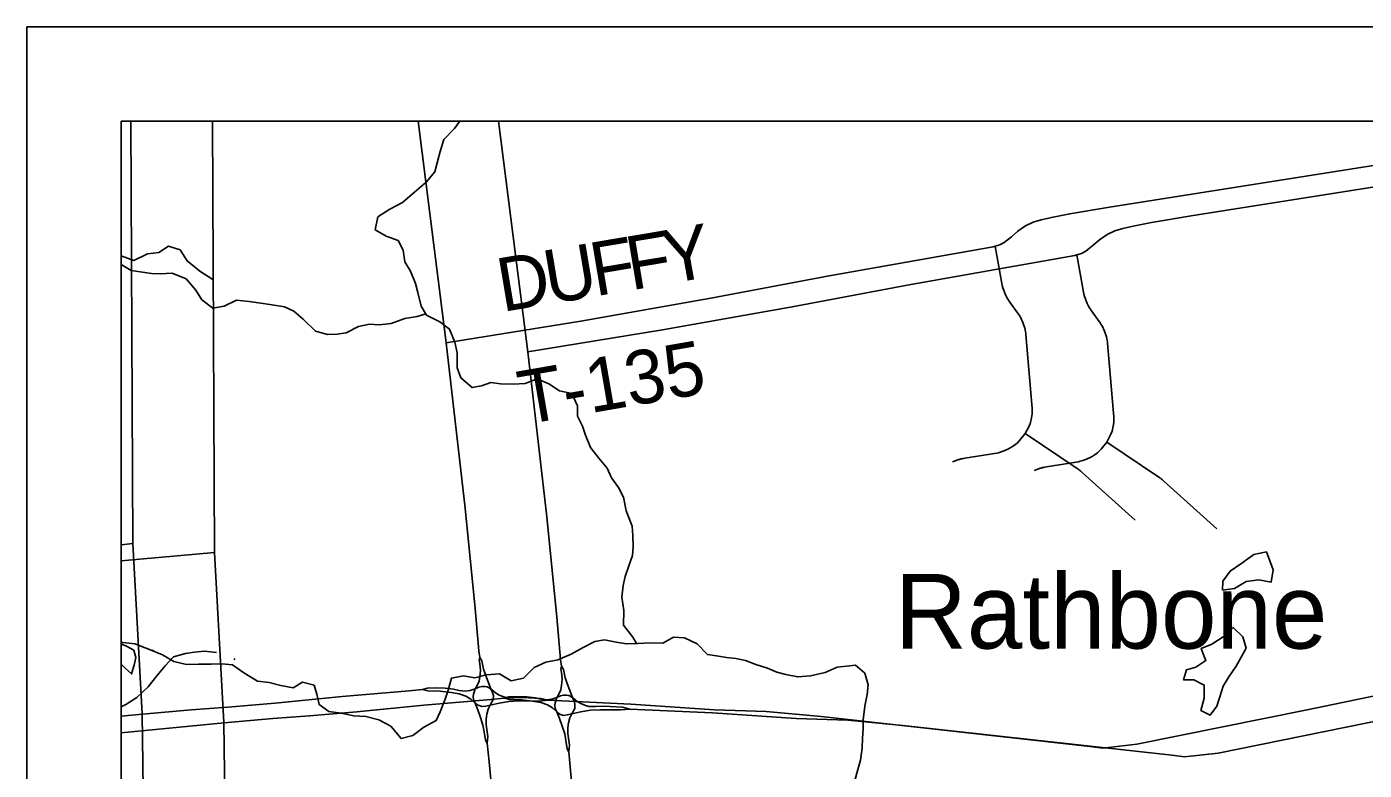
# Model space of a CAD drawing. Extents: x -38.2 to 41.9, y -4 to 24.9.
# Drawn here: x 2 to 3.416, y 20.213 to 21 of the extents above; entities that cross this region are included whole.
import ezdxf

# ---------------------------------------------------------------- set-up
doc = ezdxf.new("R2010")
doc.units = 0
for name, color, linetype in [('GM_X_County_Road', 7, 'Continuous'), ('GM_X_Interchange_Ramps', 7, 'Continuous'), ('GM_X_Minor_Lake', 7, 'Continuous'), ('GM_X_Minor_River', 7, 'Continuous'), ('GM_X_Minor_River_Text', 7, 'Continuous'), ('GM_X_State_Location', 7, 'Continuous'), ('GM_X_Township_Road', 7, 'Continuous'), ('GM_X_Township_Road_Text', 7, 'Continuous'), ('GM_X_Unincorporated_Text', 7, 'Continuous'), ('SH_Cut_Line', 7, 'Continuous'), ('SH_Data', 7, 'Continuous')]:
    doc.layers.add(name, color=color, linetype=linetype)

msp = doc.modelspace()

# ---------------------------------------------------------------- linework, layer by layer
at = {"layer": 'GM_X_County_Road'}
msp.add_line((2.1, 20.2698), (2.1225, 20.272), dxfattribs=at)
for points in [[(2.4799, 20.3319), (2.4788, 20.3391), (2.4748, 20.3839), (2.4641, 20.4903), (2.444, 20.6651), (2.4144, 20.9)], [(2.475, 20.2988), (2.4766, 20.3017), (2.4789, 20.307), (2.4802, 20.3143), (2.4805, 20.3187), (2.4798, 20.3255), (2.479, 20.3291), (2.4799, 20.3319)], [(2.4914, 20.299), (2.4869, 20.3108), (2.4837, 20.3198), (2.4818, 20.3286), (2.4799, 20.3319)], [(2.1225, 20.272), (2.1741, 20.2765), (2.2129, 20.2796), (2.263, 20.2837), (2.334, 20.2907), (2.4051, 20.2968), (2.4191, 20.2981)], [(2.4191, 20.2981), (2.4244, 20.2997), (2.4335, 20.3), (2.443, 20.2996), (2.452, 20.2984), (2.458, 20.297), (2.4641, 20.2965), (2.4694, 20.2972), (2.475, 20.2988)], [(2.4191, 20.2981), (2.4248, 20.2968), (2.4377, 20.2965), (2.4493, 20.2949), (2.4578, 20.2935), (2.4648, 20.2911), (2.4702, 20.2879), (2.4748, 20.2837)], [(2.4748, 20.2837), (2.4732, 20.2874), (2.4727, 20.2907), (2.473, 20.2932), (2.4736, 20.2953), (2.475, 20.2988)], [(2.475, 20.2988), (2.4786, 20.3005), (2.4819, 20.3013), (2.485, 20.3014), (2.4874, 20.3009), (2.4914, 20.299)], [(2.4907, 20.2817), (2.4938, 20.2874), (2.4941, 20.2917), (2.4931, 20.2949), (2.4914, 20.299)], [(2.4914, 20.299), (2.4962, 20.2946), (2.5001, 20.2923), (2.5052, 20.2905), (2.5088, 20.2895), (2.5161, 20.2892), (2.5244, 20.2896), (2.5312, 20.2894), (2.5442, 20.2887), (2.5521, 20.2867)], [(2.5521, 20.2867), (2.6398, 20.2826), (2.7282, 20.2767), (2.7828, 20.2748), (2.8413, 20.2694), (3.126, 20.2377), (3.1394, 20.236), (3.1753, 20.2401), (3.3558, 20.2767), (3.47, 20.3002), (3.5, 20.3062), (3.5061, 20.3069)], [(2.4748, 20.2837), (2.4779, 20.2814), (2.4818, 20.28), (2.486, 20.2804), (2.4907, 20.2817)], [(2.4876, 20.2415), (2.4859, 20.2446), (2.4844, 20.2533), (2.4831, 20.2604), (2.4806, 20.2685), (2.4775, 20.2765), (2.4748, 20.2837)], [(2.4876, 20.2415), (2.4882, 20.2483), (2.4863, 20.2609), (2.4864, 20.2668), (2.4872, 20.2722), (2.4885, 20.2773), (2.4907, 20.2817)], [(2.4907, 20.2817), (2.5003, 20.2838), (2.5106, 20.2855), (2.5209, 20.286), (2.5422, 20.2857), (2.5521, 20.2867)], [(2.7015, 19.4355), (2.6464, 19.9755), (2.6416, 20.0251), (2.6399, 20.0297), (2.6373, 20.0331), (2.6311, 20.0337), (2.5636, 20.0217), (2.531, 20.0146), (2.5216, 20.0146), (2.5162, 20.0164), (2.5108, 20.0203), (2.5077, 20.0277), (2.4972, 20.143), (2.4895, 20.2217), (2.4876, 20.2415)]]:
    msp.add_lwpolyline(points, dxfattribs=at)
at = {"layer": 'GM_X_Interchange_Ramps'}
for points in [[(2.1103, 20.9), (2.1, 20.9), (2.1, 20.4515), (2.1124, 20.4526)], [(2.1968, 20.9), (2.1, 20.9), (2.1, 20.4344), (2.1989, 20.4434)], [(2.1, 20.4515), (2.1, 14.1636), (2.1303, 14.1626), (2.1303, 14.1722), (2.1335, 15.4167), (2.1334, 15.4951), (2.1328, 15.831), (2.1521, 16.6664), (2.1489, 17.073), (2.1485, 17.1357), (2.1484, 17.1455), (2.1486, 17.1556), (2.1569, 17.5704), (2.1549, 17.5972), (2.1521, 17.6416), (2.1422, 17.7563), (2.1427, 17.838), (2.1429, 18.1709), (2.1421, 18.2952), (2.138, 18.8976), (2.1339, 19.396), (2.1223, 20.2725), (2.1124, 20.4526)], [(2.1, 20.4344), (2.1, 14.1575), (2.2168, 14.1534), (2.2168, 14.163), (2.22, 15.4075), (2.2199, 15.4859), (2.2193, 15.8218), (2.2386, 16.6572), (2.2354, 17.0638), (2.235, 17.1266), (2.2349, 17.1363), (2.2351, 17.1464), (2.2434, 17.5612), (2.2414, 17.5881), (2.2386, 17.6324), (2.2287, 17.7471), (2.2291, 17.8288), (2.2294, 18.1617), (2.2286, 18.286), (2.2245, 18.8884), (2.2204, 19.3868), (2.2088, 20.2633), (2.1989, 20.4434)]]:
    msp.add_lwpolyline(points, close=True, dxfattribs=at)
for points in [[(5.0183, 19.2401), (5.0869, 20.3321), (5.1243, 20.9), (2.1103, 20.9), (2.1124, 20.4526), (2.1223, 20.2725), (2.1339, 19.396)], [(5.1048, 19.2309), (5.1734, 20.3229), (5.2114, 20.9), (2.1968, 20.9), (2.1989, 20.4434), (2.2088, 20.2633), (2.2204, 19.3868)]]:
    msp.add_lwpolyline(points, dxfattribs=at)
at = {"layer": 'GM_X_Minor_Lake'}
for points in [[(3.2661, 20.4034), (3.2787, 20.4052), (3.2912, 20.4124), (3.3045, 20.4143), (3.3178, 20.4119), (3.3197, 20.4248), (3.3126, 20.4438)], [(3.3126, 20.4438), (3.2993, 20.4412), (3.2867, 20.4321), (3.2742, 20.4235), (3.2665, 20.4129), (3.2661, 20.4034)], [(3.2914, 20.3419), (3.2876, 20.354), (3.2774, 20.3639), (3.2668, 20.3541), (3.255, 20.3461), (3.2436, 20.3416), (3.2467, 20.3332)], [(3.2467, 20.3332), (3.2485, 20.3287), (3.2378, 20.3219), (3.2279, 20.3189), (3.2249, 20.3083), (3.2359, 20.3083), (3.2469, 20.3029), (3.2468, 20.2889), (3.2434, 20.276), (3.2532, 20.271), (3.2601, 20.2805), (3.2632, 20.2904), (3.267, 20.3017), (3.2727, 20.3116), (3.2807, 20.3229), (3.2914, 20.3419)]]:
    msp.add_lwpolyline(points, dxfattribs=at)
at = {"layer": 'GM_X_Minor_River'}
msp.add_line((2.1104, 20.7417), (2.1, 20.7484), dxfattribs=at)
for points in [[(2.6457, 20.3468), (2.6419, 20.3537), (2.632, 20.3662), (2.6324, 20.3818), (2.6302, 20.3958), (2.6314, 20.4083), (2.6337, 20.4178), (2.6371, 20.428), (2.6413, 20.4402), (2.6421, 20.4496), (2.6418, 20.4614), (2.6411, 20.4713), (2.6346, 20.4872), (2.632, 20.502), (2.6267, 20.5119), (2.6192, 20.5222), (2.6147, 20.5324), (2.6056, 20.5431), (2.5969, 20.5545), (2.5916, 20.5674), (2.5886, 20.5769), (2.5833, 20.5875), (2.5833, 20.5985), (2.5773, 20.6115), (2.564, 20.6145), (2.553, 20.6218), (2.5405, 20.6271), (2.5276, 20.6222), (2.5154, 20.6215), (2.5018, 20.6219), (2.4915, 20.6231), (2.4817, 20.6197), (2.4718, 20.6178), (2.4597, 20.6281), (2.4559, 20.6388), (2.4556, 20.6547), (2.4533, 20.6661), (2.4477, 20.6798), (2.4374, 20.6874), (2.4234, 20.6946), (2.4177, 20.7041), (2.414, 20.7186), (2.4117, 20.7281), (2.4064, 20.741), (2.4004, 20.7509), (2.3985, 20.7634), (2.3932, 20.7736), (2.3807, 20.7782), (2.369, 20.7851), (2.3717, 20.7987), (2.3846, 20.8067), (2.3979, 20.8138), (2.4105, 20.8248), (2.423, 20.8354), (2.4322, 20.8464), (2.4345, 20.8559), (2.4376, 20.868), (2.4418, 20.8805), (2.4528, 20.8922), (2.4587, 20.9)], [(2.4226, 20.696), (2.4135, 20.6931), (2.4002, 20.6909), (2.3858, 20.6856), (2.3733, 20.6845), (2.363, 20.6849), (2.3512, 20.6827), (2.3383, 20.6759), (2.3288, 20.6744), (2.3186, 20.6741), (2.3057, 20.6775), (2.2928, 20.6905), (2.2829, 20.6988), (2.2731, 20.7034), (2.2598, 20.7054), (2.2454, 20.7077), (2.2355, 20.7092), (2.2222, 20.7104), (2.2089, 20.704), (2.1972, 20.7021), (2.1854, 20.7109), (2.179, 20.7212), (2.1688, 20.733), (2.154, 20.7391), (2.1414, 20.7383), (2.132, 20.7388), (2.1104, 20.7417)], [(2.8764, 20.2005), (2.8802, 20.2134), (2.8829, 20.2232), (2.8845, 20.2365), (2.8849, 20.2464), (2.8857, 20.2566), (2.8857, 20.2661), (2.8873, 20.2805), (2.89, 20.293), (2.8908, 20.3032), (2.8874, 20.3154), (2.8775, 20.3241), (2.868, 20.3227), (2.8582, 20.3219), (2.8456, 20.3163), (2.83, 20.3125), (2.8164, 20.3114), (2.8039, 20.3141), (2.7944, 20.3164), (2.7845, 20.3206), (2.772, 20.3245), (2.761, 20.3287), (2.7507, 20.331), (2.7409, 20.3321), (2.7303, 20.3337), (2.7208, 20.3352), (2.7098, 20.3466), (2.6965, 20.3528), (2.6848, 20.3536), (2.6737, 20.3471), (2.6604, 20.3476), (2.6472, 20.3468), (2.635, 20.3465), (2.624, 20.3484), (2.6119, 20.3507), (2.6016, 20.3489), (2.5891, 20.3425), (2.5765, 20.3357), (2.5624, 20.3296), (2.5495, 20.327), (2.5374, 20.3214), (2.5259, 20.31), (2.513, 20.3074), (2.5005, 20.3147), (2.4868, 20.3136), (2.4743, 20.3106), (2.4625, 20.3125), (2.4496, 20.3103), (2.4462, 20.2974), (2.4431, 20.2879), (2.4378, 20.2746), (2.4336, 20.2652), (2.4206, 20.2584), (2.4088, 20.2493), (2.3963, 20.2463), (2.3857, 20.2593), (2.3728, 20.2661), (2.3592, 20.2696), (2.3463, 20.2704), (2.333, 20.2731), (2.3197, 20.275), (2.3095, 20.2822), (2.3072, 20.2932), (2.3042, 20.3027), (2.2921, 20.3058), (2.2822, 20.2998), (2.2689, 20.3025), (2.2568, 20.3055), (2.2442, 20.3071), (2.2298, 20.3159), (2.2177, 20.3242), (2.2067, 20.3254), (2.1953, 20.3251), (2.182, 20.3251), (2.1691, 20.3248), (2.1558, 20.3278), (2.1437, 20.3347), (2.1301, 20.3404), (2.1144, 20.3466)], [(2.1144, 20.3466), (2.1016, 20.348), (2.1, 20.3478)], [(2.1131, 20.3217), (2.1137, 20.3238), (2.1156, 20.3321), (2.1133, 20.3397), (2.105, 20.3443), (2.1, 20.3463)], [(2.1332, 20.3386), (2.134, 20.3401)], [(2.1, 20.325), (2.1042, 20.3207), (2.111, 20.3147), (2.1131, 20.3217)]]:
    msp.add_lwpolyline(points, dxfattribs=at)
at = {"layer": 'GM_X_Minor_River_Text'}
for points in [[(2.1969, 20.7325), (2.1832, 20.7413), (2.1699, 20.752), (2.1624, 20.7638), (2.1502, 20.7676), (2.14, 20.7611), (2.1278, 20.7596), (2.1134, 20.7525), (2.1, 20.7575)], [(2.2009, 20.3375), (2.1881, 20.3388), (2.1778, 20.3377), (2.168, 20.3362), (2.1554, 20.3328), (2.1467, 20.3233), (2.1376, 20.3127), (2.1284, 20.301), (2.1167, 20.2896), (2.1049, 20.2821), (2.1, 20.2797)], [(2.2197, 20.3294), (2.2205, 20.3309)]]:
    msp.add_lwpolyline(points, dxfattribs=at)
at = {"layer": 'GM_X_State_Location'}
for points in [[(2.5305, 20.6559), (2.6733, 20.679), (2.8106, 20.7035), (2.9362, 20.727), (3.1099, 20.7577), (3.1121, 20.7584), (3.1169, 20.76), (3.1216, 20.7624), (3.1292, 20.7686), (3.1361, 20.7744), (3.1441, 20.7801), (3.1523, 20.7839), (3.1606, 20.7862), (3.1714, 20.7889), (3.1909, 20.7927), (3.233, 20.7996), (3.5146, 20.8441)], [(3.0666, 20.5299), (3.0706, 20.5316), (3.073, 20.5324), (3.0741, 20.5327), (3.0754, 20.5331), (3.077, 20.5334), (3.0783, 20.5337), (3.0798, 20.5339), (3.1112, 20.5389), (3.1138, 20.5394), (3.1154, 20.5398), (3.1182, 20.5405), (3.1205, 20.5413), (3.123, 20.5423), (3.1254, 20.5435), (3.128, 20.5449), (3.1302, 20.5462), (3.1337, 20.5488), (3.1355, 20.5504), (3.1378, 20.5526), (3.1438, 20.5601), (3.1477, 20.5677), (3.1492, 20.5718), (3.1504, 20.5769), (3.151, 20.581), (3.1512, 20.5839), (3.1512, 20.5868), (3.1509, 20.5909), (3.1444, 20.6648), (3.1443, 20.6663), (3.1441, 20.6676), (3.1437, 20.6699), (3.1432, 20.6717), (3.1427, 20.6737), (3.1421, 20.6756), (3.1413, 20.6776), (3.1406, 20.6793), (3.1399, 20.6808), (3.139, 20.6825), (3.1384, 20.6837), (3.1375, 20.6851), (3.1365, 20.6866), (3.1356, 20.688), (3.1274, 20.6992), (3.1267, 20.7003), (3.1254, 20.7023), (3.124, 20.7047), (3.1228, 20.707), (3.1217, 20.7097), (3.1207, 20.7124), (3.1201, 20.7144), (3.1195, 20.7168), (3.1191, 20.7189), (3.1121, 20.7584)], [(3.1438, 20.5601), (3.1986, 20.5231), (3.1994, 20.5226), (3.2002, 20.522), (3.2009, 20.5215), (3.2015, 20.521), (3.2022, 20.5205), (3.2031, 20.5197), (3.204, 20.5189), (3.2601, 20.4683)]]:
    msp.add_lwpolyline(points, dxfattribs=at)
at = {"layer": 'GM_X_Township_Road'}
for points in [[(2.444, 20.6651), (2.5868, 20.6882), (2.7242, 20.7127), (2.8497, 20.7362), (3.0234, 20.7669), (3.0256, 20.7676), (3.0304, 20.7692), (3.0351, 20.7716), (3.0428, 20.7777), (3.0496, 20.7836), (3.0576, 20.7892), (3.0658, 20.7931), (3.0742, 20.7954), (3.085, 20.7981), (3.1045, 20.8019), (3.1465, 20.8088), (3.4281, 20.8533)], [(2.9801, 20.5391), (2.9841, 20.5408), (2.9865, 20.5416), (2.9877, 20.5419), (2.989, 20.5423), (2.9905, 20.5426), (2.9918, 20.5429), (2.9933, 20.5431), (3.0248, 20.5481), (3.0273, 20.5486), (3.0289, 20.5489), (3.0317, 20.5497), (3.034, 20.5505), (3.0365, 20.5515), (3.039, 20.5527), (3.0415, 20.5541), (3.0437, 20.5554), (3.0472, 20.558), (3.049, 20.5595), (3.0513, 20.5618), (3.0573, 20.5693), (3.0613, 20.5769), (3.0627, 20.581), (3.0639, 20.586), (3.0645, 20.5902), (3.0647, 20.5931), (3.0647, 20.596), (3.0644, 20.6001), (3.058, 20.674), (3.0578, 20.6755), (3.0576, 20.6768), (3.0572, 20.6791), (3.0568, 20.6809), (3.0562, 20.6829), (3.0556, 20.6848), (3.0548, 20.6868), (3.0541, 20.6885), (3.0534, 20.6899), (3.0525, 20.6917), (3.0519, 20.6929), (3.0511, 20.6943), (3.0501, 20.6958), (3.0491, 20.6972), (3.0409, 20.7084), (3.0402, 20.7095), (3.0389, 20.7115), (3.0375, 20.7139), (3.0363, 20.7162), (3.0352, 20.7188), (3.0342, 20.7216), (3.0336, 20.7236), (3.033, 20.726), (3.0326, 20.7281), (3.0256, 20.7676)], [(3.0573, 20.5693), (3.1122, 20.5323), (3.1129, 20.5317), (3.1137, 20.5312), (3.1144, 20.5307), (3.1151, 20.5302), (3.1157, 20.5296), (3.1166, 20.5289), (3.1175, 20.5281), (3.1737, 20.4775)]]:
    msp.add_lwpolyline(points, dxfattribs=at)
at = {"layer": 'GM_X_Township_Road_Text'}
msp.add_line((2.1, 20.2521), (2.209, 20.2628), dxfattribs=at)
for points in [[(2.5664, 20.3227), (2.5653, 20.3299), (2.5613, 20.3747), (2.5506, 20.4811), (2.5305, 20.6559), (2.4997, 20.9)], [(2.5614, 20.2896), (2.563, 20.2925), (2.5654, 20.2978), (2.5667, 20.3051), (2.567, 20.3095), (2.5662, 20.3163), (2.5655, 20.3199), (2.5664, 20.3227)], [(2.5778, 20.2898), (2.5734, 20.3016), (2.5702, 20.3106), (2.5683, 20.3194), (2.5664, 20.3227)], [(2.6386, 20.2775), (2.7263, 20.2734), (2.8147, 20.2675), (2.8693, 20.2656), (2.9277, 20.2602), (3.2124, 20.2285), (3.2258, 20.2268), (3.2617, 20.2309), (3.4423, 20.2675), (3.5565, 20.2911), (3.5864, 20.297), (3.5926, 20.2977)], [(2.209, 20.2628), (2.2605, 20.2673), (2.2994, 20.2704), (2.3495, 20.2745), (2.4205, 20.2815), (2.4916, 20.2876), (2.5056, 20.2889)], [(2.5056, 20.2889), (2.5109, 20.2905), (2.52, 20.2908), (2.5294, 20.2905), (2.5385, 20.2892), (2.5445, 20.2878), (2.5505, 20.2873), (2.5559, 20.288), (2.5614, 20.2896)], [(2.5056, 20.2889), (2.5113, 20.2876), (2.5242, 20.2873), (2.5357, 20.2857), (2.5443, 20.2843), (2.5513, 20.2819), (2.5567, 20.2787), (2.5613, 20.2746)], [(2.5613, 20.2746), (2.5597, 20.2782), (2.5592, 20.2816), (2.5594, 20.284), (2.5601, 20.2861), (2.5614, 20.2896)], [(2.5614, 20.2896), (2.5651, 20.2913), (2.5684, 20.2921), (2.5715, 20.2922), (2.5739, 20.2917), (2.5778, 20.2898)], [(2.5772, 20.2725), (2.5802, 20.2782), (2.5805, 20.2825), (2.5796, 20.2857), (2.5778, 20.2898)], [(2.5778, 20.2898), (2.5827, 20.2854), (2.5866, 20.2832), (2.5917, 20.2813), (2.5953, 20.2803), (2.6025, 20.28), (2.6109, 20.2804), (2.6176, 20.2803), (2.6307, 20.2795), (2.6386, 20.2775)], [(2.5613, 20.2746), (2.5643, 20.2722), (2.5683, 20.2708), (2.5724, 20.2712), (2.5772, 20.2725)], [(2.574, 20.2323), (2.5724, 20.2354), (2.5709, 20.2441), (2.5696, 20.2512), (2.5671, 20.2593), (2.564, 20.2673), (2.5613, 20.2746)], [(2.574, 20.2323), (2.5747, 20.2392), (2.5728, 20.2517), (2.5729, 20.2576), (2.5737, 20.263), (2.575, 20.2681), (2.5772, 20.2725)], [(2.5772, 20.2725), (2.5867, 20.2746), (2.5971, 20.2763), (2.6074, 20.2768), (2.6287, 20.2765), (2.6386, 20.2775)], [(2.7879, 19.4263), (2.7328, 19.9663), (2.728, 20.016), (2.7263, 20.0205), (2.7238, 20.0239), (2.7175, 20.0245), (2.65, 20.0126), (2.6174, 20.0055), (2.6081, 20.0055), (2.6027, 20.0072), (2.5973, 20.0111), (2.5942, 20.0185), (2.5836, 20.1338), (2.5759, 20.2125), (2.574, 20.2323)]]:
    msp.add_lwpolyline(points, dxfattribs=at)
at = {"layer": 'SH_Cut_Line'}
msp.add_lwpolyline([(2.1103, 20.9), (2.1, 20.9), (2.1, 14.1636), (2.1303, 14.1626), (2.1303, 14.1722), (2.1335, 15.4167), (2.1334, 15.4951), (2.1328, 15.831), (2.1521, 16.6664), (2.1489, 17.073), (2.1485, 17.1357), (2.1484, 17.1455), (2.1486, 17.1556), (2.1569, 17.5704), (2.1549, 17.5972), (2.1521, 17.6416), (2.1422, 17.7563), (2.1427, 17.838), (2.1429, 18.1709), (2.1421, 18.2952), (2.138, 18.8976), (2.1339, 19.396), (2.1223, 20.2725), (2.1124, 20.4526)], close=True, dxfattribs=at)
msp.add_lwpolyline([(8.9, 20.9), (2.1103, 20.9), (2.1124, 20.4526), (2.1223, 20.2725), (2.1339, 19.396), (2.138, 18.8976), (2.1421, 18.2952), (2.1429, 18.1709), (2.1427, 17.838), (2.1422, 17.7563), (2.1521, 17.6416), (2.1549, 17.5972), (2.1569, 17.5704), (2.1486, 17.1556)], dxfattribs=at)
at = {"layer": 'SH_Data'}
for p, q in [((2, 21), (9, 21)), ((2, 21), (2, 14)), ((2.1, 20.9), (2.1, 14.1)), ((2.1, 20.9), (8.9, 20.9))]:
    msp.add_line(p, q, dxfattribs=at)

# ---------------------------------------------------------------- texts
at = {"layer": 'GM_X_Township_Road_Text'}
for s, height, rotation, p in [('Y', 0.0568, 10.1623, (2.6783, 20.7273)), ('F', 0.0568, 9.5662, (2.602, 20.7145)), ('F', 0.0568, 9.5774, (2.6399, 20.7208)), ('U', 0.0568, 9.5688, (2.5527, 20.7061)), ('D', 0.0568, 9.5665, (2.5034, 20.6978)), ('T-135', 0.05682, 9.8775, (2.5261, 20.5784))]:
    msp.add_text(s, height=height, rotation=rotation, dxfattribs=at).set_placement(p)
at = {"layer": 'GM_X_Unincorporated_Text'}
msp.add_text('Rathbone', height=0.07898, rotation=0, dxfattribs=at).set_placement((2.9192, 20.3415))

doc.saveas('drawing.dxf')
